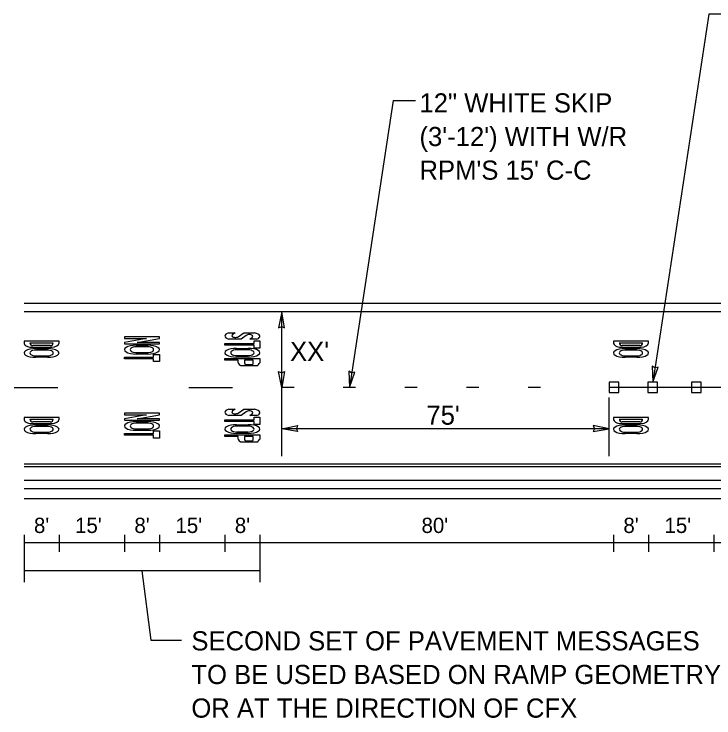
# Model space of a CAD drawing. Extents: x 583689 to 590775, y 1496016 to 1497365.
# Drawn here: x 587322.5 to 587578.1, y 1496182.9 to 1496440 of the extents above; entities that cross this region are included whole.
import ezdxf

# ---------------------------------------------------------------- set-up
doc = ezdxf.new("R2010")
doc.units = 0
for name, color, linetype in [('10', 7, 'Continuous'), ('2', 7, 'Continuous'), ('21', 7, 'Continuous'), ('41', 7, 'Continuous'), ('42', 7, 'Continuous'), ('46', 7, 'Continuous'), ('52', 7, 'Continuous'), ('PavtMessage', 7, 'Continuous'), ('PMStripe6W(10-30)', 7, 'Continuous'), ('TextLabel', 7, 'Continuous')]:
    doc.layers.add(name, color=color, linetype=linetype)

msp = doc.modelspace()

# ---------------------------------------------------------------- linework, layer by layer
at = {"layer": '10'}
for p, q in [((587424.74, 1496303.64), (587420.24, 1496303.64)), ((587447.24, 1496303.64), (587442.74, 1496303.64)), ((587469.74, 1496303.64), (587465.24, 1496303.64)), ((587492.24, 1496303.64), (587487.74, 1496303.64)), ((587514.74, 1496303.64), (587510.24, 1496303.64))]:
    msp.add_line(p, q, dxfattribs=at)
at = {"layer": '2'}
for p, q in [((587663.57, 1496331.25), (587326.15, 1496331.25)), ((587635.53, 1496303.64), (587539.85, 1496303.64)), ((587326.15, 1496274.75), (587663.58, 1496274.75)), ((587387.69, 1496275.75), (587663.57, 1496275.75))]:
    msp.add_line(p, q, dxfattribs=at)
for points in [[(587539.85, 1496301.74), (587543.4, 1496301.74), (587543.4, 1496305.54), (587539.85, 1496305.54)], [(587554.02, 1496301.74), (587557.57, 1496301.74), (587557.57, 1496305.54), (587554.02, 1496305.54)], [(587569.96, 1496301.74), (587573.52, 1496301.74), (587573.52, 1496305.54), (587569.97, 1496305.54)]]:
    msp.add_lwpolyline(points, close=True, dxfattribs=at)
at = {"layer": '21'}
for p, q in [((587576.23, 1496440.04), (587555.8, 1496305.54)), ((587583.82, 1496440.04), (587576.23, 1496440.04)), ((587460.91, 1496408.42), (587444.99, 1496303.64)), ((587460.91, 1496408.42), (587469.14, 1496408.42)), ((587420.24, 1496278.52), (587420.24, 1496331.25)), ((587539.85, 1496278.52), (587539.85, 1496300.03)), ((587539.85, 1496288.57), (587420.24, 1496288.57)), ((587326.15, 1496249.83), (587326.15, 1496232.5)), ((587338.9, 1496249.83), (587338.9, 1496243.54)), ((587362.83, 1496249.83), (587362.83, 1496243.54)), ((587375.58, 1496249.83), (587375.58, 1496243.54)), ((587399.51, 1496249.83), (587399.51, 1496243.54)), ((587412.26, 1496249.83), (587412.26, 1496232.5)), ((587541.44, 1496249.83), (587541.44, 1496243.54)), ((587554.2, 1496249.83), (587554.2, 1496243.54)), ((587578.12, 1496249.83), (587578.12, 1496243.54)), ((587412.26, 1496246.88), (587326.15, 1496246.88)), ((587541.44, 1496246.88), (587412.26, 1496246.88)), ((587635.53, 1496246.88), (587541.44, 1496246.88)), ((587412.26, 1496236.69), (587326.15, 1496236.69)), ((587369.21, 1496236.69), (587372.4, 1496211.31)), ((587372.4, 1496211.31), (587383.61, 1496211.31))]:
    msp.add_line(p, q, dxfattribs=at)
at = {"layer": '41'}
msp.add_line((587326.15, 1496275.75), (587663.57, 1496275.75), dxfattribs=at)
at = {"layer": '42'}
for p, q in [((587663.57, 1496334.25), (587326.15, 1496334.25)), ((587326.15, 1496269.75), (587663.57, 1496269.75)), ((587663.57, 1496263), (587326.15, 1496263))]:
    msp.add_line(p, q, dxfattribs=at)
at = {"layer": '46'}
msp.add_line((587326.15, 1496266.75), (587663.57, 1496266.75), dxfattribs=at)
at = {"layer": '52'}
for p, q in [((587420.24, 1496331.25), (587419.12, 1496325.45)), ((587421.32, 1496325.45), (587420.24, 1496331.25)), ((587419.12, 1496325.45), (587420.24, 1496325.89)), ((587420.24, 1496325.89), (587421.32, 1496325.45)), ((587420.24, 1496303.64), (587419.12, 1496309.44)), ((587419.12, 1496309.44), (587420.24, 1496309)), ((587420.24, 1496309), (587421.32, 1496309.44)), ((587421.32, 1496309.44), (587420.24, 1496303.64)), ((587445.79, 1496308.94), (587444.79, 1496309.53)), ((587444.79, 1496309.53), (587444.99, 1496303.64)), ((587556.6, 1496310.84), (587555.6, 1496311.43)), ((587555.6, 1496311.43), (587555.8, 1496305.54)), ((587555.8, 1496305.54), (587557.77, 1496311.1)), ((587557.77, 1496311.1), (587556.6, 1496310.84)), ((587444.99, 1496303.64), (587446.97, 1496309.2)), ((587446.97, 1496309.2), (587445.79, 1496308.94)), ((587420.24, 1496288.57), (587426.04, 1496289.69)), ((587426.04, 1496289.69), (587425.6, 1496288.57)), ((587539.85, 1496288.57), (587534.05, 1496289.69)), ((587534.05, 1496289.69), (587534.49, 1496288.57)), ((587426.04, 1496287.49), (587420.24, 1496288.57)), ((587425.6, 1496288.57), (587426.04, 1496287.49)), ((587534.49, 1496288.57), (587534.05, 1496287.49)), ((587534.05, 1496287.49), (587539.85, 1496288.57))]:
    msp.add_line(p, q, dxfattribs=at)
at = {"layer": 'PavtMessage'}
for p, q in [((587400.95, 1496323.63), (587403.27, 1496323.63)), ((587403.27, 1496323.63), (587402.26, 1496322.97)), ((587404.4, 1496322.18), (587406.46, 1496323.63)), ((587407.25, 1496322.66), (587405.41, 1496321.24)), ((587406.46, 1496323.63), (587410.36, 1496323.63)), ((587338.91, 1496320.51), (587326.15, 1496320.51)), ((587326.15, 1496320.51), (587326.15, 1496319.97)), ((587328.28, 1496319.97), (587336.79, 1496319.97)), ((587338.91, 1496319.97), (587338.91, 1496320.51)), ((587375.59, 1496322.11), (587362.83, 1496322.11)), ((587362.83, 1496322.11), (587362.83, 1496321.57)), ((587362.83, 1496321.57), (587370.8, 1496321.57)), ((587370.8, 1496321.57), (587362.83, 1496320.11)), ((587362.83, 1496320.11), (587362.83, 1496319.58)), ((587367.45, 1496320.11), (587375.59, 1496321.57)), ((587375.59, 1496320.11), (587367.45, 1496320.11)), ((587375.59, 1496321.57), (587375.59, 1496322.11)), ((587375.59, 1496319.58), (587375.59, 1496320.11)), ((587405.41, 1496321.24), (587400.95, 1496321.24)), ((587408.56, 1496321.24), (587409.48, 1496321.93)), ((587411.18, 1496321.24), (587408.56, 1496321.24)), ((587410.14, 1496320.71), (587412.26, 1496320.71)), ((587410.14, 1496319.64), (587410.14, 1496320.71)), ((587412.26, 1496320.71), (587412.26, 1496318.05)), ((587554.2, 1496320.51), (587541.45, 1496320.51)), ((587541.45, 1496320.51), (587541.45, 1496319.97)), ((587543.57, 1496319.97), (587552.08, 1496319.97)), ((587554.2, 1496319.97), (587554.2, 1496320.51)), ((587328.81, 1496318.38), (587336.25, 1496318.38)), ((587335.72, 1496318.91), (587329.34, 1496318.91)), ((587330.4, 1496317.85), (587334.66, 1496317.85)), ((587334.66, 1496317.32), (587330.4, 1496317.32)), ((587362.83, 1496319.58), (587375.59, 1496319.58)), ((587367.08, 1496319.05), (587371.33, 1496319.05)), ((587371.33, 1496318.52), (587367.08, 1496318.52)), ((587399.51, 1496319.11), (587399.51, 1496319.64)), ((587399.51, 1496319.64), (587410.14, 1496319.64)), ((587410.14, 1496319.11), (587399.51, 1496319.11)), ((587403.76, 1496317.92), (587408.01, 1496317.92)), ((587408.01, 1496317.38), (587403.76, 1496317.38)), ((587410.14, 1496318.05), (587410.14, 1496319.11)), ((587412.26, 1496318.05), (587410.14, 1496318.05)), ((587544.1, 1496318.38), (587551.55, 1496318.38)), ((587551.01, 1496318.91), (587544.64, 1496318.91)), ((587545.7, 1496317.85), (587549.95, 1496317.85)), ((587549.95, 1496317.32), (587545.7, 1496317.32)), ((587330.4, 1496315.19), (587334.66, 1496315.19)), ((587334.66, 1496314.66), (587330.4, 1496314.66)), ((587362.83, 1496314.12), (587362.83, 1496314.65)), ((587362.83, 1496314.65), (587373.46, 1496314.65)), ((587367.08, 1496316.39), (587371.33, 1496316.39)), ((587371.33, 1496315.86), (587367.08, 1496315.86)), ((587373.46, 1496315.72), (587375.59, 1496315.72)), ((587373.46, 1496314.65), (587373.46, 1496315.72)), ((587375.59, 1496315.72), (587375.59, 1496313.06)), ((587403.76, 1496315.26), (587408.01, 1496315.26)), ((587408.01, 1496314.73), (587403.76, 1496314.73)), ((587545.7, 1496315.19), (587549.95, 1496315.19)), ((587549.95, 1496314.66), (587545.7, 1496314.66)), ((587373.46, 1496314.12), (587362.83, 1496314.12)), ((587373.46, 1496313.06), (587373.46, 1496314.12)), ((587375.59, 1496313.06), (587373.46, 1496313.06)), ((587399.51, 1496314.19), (587412.26, 1496314.19)), ((587399.51, 1496313.66), (587399.51, 1496314.19)), ((587404.29, 1496313.66), (587399.51, 1496313.66)), ((587404.29, 1496312.65), (587404.29, 1496313.66)), ((587409.87, 1496313.66), (587406.68, 1496313.66)), ((587406.68, 1496313.66), (587406.68, 1496312.6)), ((587407.09, 1496312.07), (587409.47, 1496312.07)), ((587409.87, 1496312.6), (587409.87, 1496313.66)), ((587412.26, 1496314.19), (587412.26, 1496312.65)), ((587411.2, 1496311.54), (587405.36, 1496311.54)), ((587375.59, 1496294.22), (587362.83, 1496294.22)), ((587362.83, 1496294.22), (587362.83, 1496293.69)), ((587375.59, 1496293.69), (587375.59, 1496294.22)), ((587400.95, 1496295.74), (587403.27, 1496295.74)), ((587403.27, 1496295.74), (587402.26, 1496295.08)), ((587404.4, 1496294.29), (587406.46, 1496295.74)), ((587407.25, 1496294.77), (587405.41, 1496293.35)), ((587406.46, 1496295.74), (587410.36, 1496295.74)), ((587408.56, 1496293.35), (587409.48, 1496294.05)), ((587338.91, 1496292.62), (587326.15, 1496292.62)), ((587326.15, 1496292.62), (587326.15, 1496292.09)), ((587328.28, 1496292.09), (587336.79, 1496292.09)), ((587338.91, 1496292.09), (587338.91, 1496292.62)), ((587362.83, 1496293.69), (587370.8, 1496293.69)), ((587370.8, 1496293.69), (587362.83, 1496292.22)), ((587362.83, 1496292.22), (587362.83, 1496291.69)), ((587362.83, 1496291.69), (587375.59, 1496291.69)), ((587367.45, 1496292.22), (587375.59, 1496293.69)), ((587375.59, 1496292.22), (587367.45, 1496292.22)), ((587375.59, 1496291.69), (587375.59, 1496292.22)), ((587399.51, 1496291.22), (587399.51, 1496291.76)), ((587399.51, 1496291.76), (587410.14, 1496291.76)), ((587405.41, 1496293.35), (587400.95, 1496293.35)), ((587411.18, 1496293.35), (587408.56, 1496293.35)), ((587410.14, 1496292.82), (587412.26, 1496292.82)), ((587410.14, 1496291.76), (587410.14, 1496292.82)), ((587412.26, 1496292.82), (587412.26, 1496290.16)), ((587554.2, 1496292.62), (587541.45, 1496292.62)), ((587541.45, 1496292.62), (587541.45, 1496292.09)), ((587543.57, 1496292.09), (587552.08, 1496292.09)), ((587554.2, 1496292.09), (587554.2, 1496292.62)), ((587328.81, 1496290.49), (587336.25, 1496290.49)), ((587335.72, 1496291.02), (587329.34, 1496291.02)), ((587330.4, 1496289.96), (587334.66, 1496289.96)), ((587334.66, 1496289.43), (587330.4, 1496289.43)), ((587367.08, 1496291.16), (587371.33, 1496291.16)), ((587371.33, 1496290.63), (587367.08, 1496290.63)), ((587410.14, 1496291.22), (587399.51, 1496291.22)), ((587403.76, 1496290.03), (587408.01, 1496290.03)), ((587408.01, 1496289.5), (587403.76, 1496289.5)), ((587410.14, 1496290.16), (587410.14, 1496291.22)), ((587412.26, 1496290.16), (587410.14, 1496290.16)), ((587544.1, 1496290.49), (587551.55, 1496290.49)), ((587551.01, 1496291.02), (587544.64, 1496291.02)), ((587545.7, 1496289.96), (587549.95, 1496289.96)), ((587549.95, 1496289.43), (587545.7, 1496289.43)), ((587330.4, 1496287.3), (587334.66, 1496287.3)), ((587334.66, 1496286.77), (587330.4, 1496286.77)), ((587362.83, 1496286.24), (587362.83, 1496286.77)), ((587362.83, 1496286.77), (587373.46, 1496286.77)), ((587367.08, 1496288.5), (587371.33, 1496288.5)), ((587371.33, 1496287.97), (587367.08, 1496287.97)), ((587373.46, 1496287.83), (587375.59, 1496287.83)), ((587373.46, 1496286.77), (587373.46, 1496287.83)), ((587375.59, 1496287.83), (587375.59, 1496285.17)), ((587399.51, 1496286.31), (587412.26, 1496286.31)), ((587399.51, 1496285.77), (587399.51, 1496286.31)), ((587403.76, 1496287.37), (587408.01, 1496287.37)), ((587408.01, 1496286.84), (587403.76, 1496286.84)), ((587412.26, 1496286.31), (587412.26, 1496284.76)), ((587545.7, 1496287.3), (587549.95, 1496287.3)), ((587549.95, 1496286.77), (587545.7, 1496286.77)), ((587373.46, 1496286.24), (587362.83, 1496286.24)), ((587373.46, 1496285.17), (587373.46, 1496286.24)), ((587375.59, 1496285.17), (587373.46, 1496285.17)), ((587404.29, 1496285.77), (587399.51, 1496285.77)), ((587404.29, 1496284.76), (587404.29, 1496285.77)), ((587409.87, 1496285.77), (587406.68, 1496285.77)), ((587406.68, 1496285.77), (587406.68, 1496284.71)), ((587407.09, 1496284.18), (587409.47, 1496284.18)), ((587409.87, 1496284.71), (587409.87, 1496285.77)), ((587411.2, 1496283.65), (587405.36, 1496283.65))]:
    msp.add_line(p, q, dxfattribs=at)
for centre, start, end in [((587329.34, 1496319.97), 180, 270), ((587335.72, 1496319.97), 270, 0), ((587544.64, 1496319.97), 180, 270), ((587551.02, 1496319.97), 270, 0), ((587329.34, 1496292.09), 180, 270), ((587335.72, 1496292.09), 270, 0), ((587544.64, 1496292.09), 180, 270), ((587551.02, 1496292.09), 270, 0)]:
    msp.add_arc(centre, 1.06, start, end, dxfattribs=at)
for centre, major_axis, ratio, start_param, end_param in [((587403.76, 1496322.43), (-4.25, 0), 0.375, 5.435123, 7.131247), ((587403.32, 1496322.57), (1.33, 0), 0.5, 2.490106, 5.666015), ((587408.37, 1496322.3), (1.33, 0), 0.5, 5.699287, 8.851109), ((587408.01, 1496322.3), (4.25, 0), 0.375, 5.553458, 7.268296), ((587328.81, 1496319.97), (2.66, 0), 0.6, 3.141593, 4.71335), ((587336.25, 1496319.97), (2.66, 0), 0.6, 4.71335, 6.283185), ((587544.1, 1496319.97), (2.66, 0), 0.6, 3.141593, 4.71335), ((587551.55, 1496319.97), (2.66, 0), 0.6, 4.71335, 6.283185), ((587330.4, 1496316.25), (4.25, 0), 0.375, 1.570796, 4.712389), ((587330.4, 1496316.25), (2.13, 0), 0.5, 1.570796, 4.712389), ((587334.66, 1496316.25), (4.25, 0), 0.375, 4.712389, 7.853982), ((587334.66, 1496316.25), (2.13, 0), 0.5, 4.712389, 7.853982), ((587367.08, 1496317.45), (4.25, 0), 0.375, 1.570796, 4.712389), ((587367.08, 1496317.45), (2.13, 0), 0.5, 1.570796, 4.712389), ((587371.33, 1496317.45), (4.25, 0), 0.375, 4.712389, 7.853982), ((587371.33, 1496317.45), (2.13, 0), 0.5, 4.712389, 7.853982), ((587403.76, 1496316.32), (4.25, 0), 0.375, 1.570796, 4.712389), ((587403.76, 1496316.32), (2.13, 0), 0.5, 1.570796, 4.712389), ((587408.01, 1496316.32), (4.25, 0), 0.375, 4.712389, 7.853982), ((587408.01, 1496316.32), (2.13, 0), 0.5, 4.712389, 7.853982), ((587545.7, 1496316.25), (4.25, 0), 0.375, 1.570796, 4.712389), ((587545.7, 1496316.25), (2.13, 0), 0.5, 1.570796, 4.712389), ((587549.95, 1496316.25), (4.25, 0), 0.375, 4.712389, 7.853982), ((587549.95, 1496316.25), (2.13, 0), 0.5, 4.712389, 7.853982), ((587408.28, 1496313.66), (4.25, 0), 0.6875, 3.497014, 3.955933), ((587408.28, 1496312.6), (1.59, 0), 0.5, 3.141593, 3.87132), ((587408.28, 1496312.6), (1.59, 0), 0.5, 5.553458, 6.283185), ((587408.28, 1496313.66), (4.25, 0), 0.6875, 5.468845, 5.927764), ((587403.76, 1496294.55), (-4.25, 0), 0.375, 5.435123, 7.131247), ((587403.32, 1496294.68), (1.33, 0), 0.5, 2.490106, 5.666015), ((587408.37, 1496294.41), (1.33, 0), 0.5, 5.699287, 8.851109), ((587408.01, 1496294.41), (4.25, 0), 0.375, 5.553458, 7.268296), ((587328.81, 1496292.09), (2.66, 0), 0.6, 3.141593, 4.71335), ((587336.25, 1496292.09), (2.66, 0), 0.6, 4.71335, 6.283185), ((587544.1, 1496292.09), (2.66, 0), 0.6, 3.141593, 4.71335), ((587551.55, 1496292.09), (2.66, 0), 0.6, 4.71335, 6.283185), ((587330.4, 1496288.37), (4.25, 0), 0.375, 1.570796, 4.712389), ((587330.4, 1496288.37), (2.13, 0), 0.5, 1.570796, 4.712389), ((587334.66, 1496288.37), (4.25, 0), 0.375, 4.712389, 7.853982), ((587334.66, 1496288.37), (2.13, 0), 0.5, 4.712389, 7.853982), ((587367.08, 1496289.57), (4.25, 0), 0.375, 1.570796, 4.712389), ((587367.08, 1496289.57), (2.13, 0), 0.5, 1.570796, 4.712389), ((587371.33, 1496289.57), (4.25, 0), 0.375, 4.712389, 7.853982), ((587371.33, 1496289.57), (2.13, 0), 0.5, 4.712389, 7.853982), ((587403.76, 1496288.43), (4.25, 0), 0.375, 1.570796, 4.712389), ((587403.76, 1496288.43), (2.13, 0), 0.5, 1.570796, 4.712389), ((587408.01, 1496288.43), (4.25, 0), 0.375, 4.712389, 7.853982), ((587408.01, 1496288.43), (2.13, 0), 0.5, 4.712389, 7.853982), ((587545.7, 1496288.37), (4.25, 0), 0.375, 1.570796, 4.712389), ((587545.7, 1496288.37), (2.13, 0), 0.5, 1.570796, 4.712389), ((587549.95, 1496288.37), (4.25, 0), 0.375, 4.712389, 7.853982), ((587549.95, 1496288.37), (2.13, 0), 0.5, 4.712389, 7.853982), ((587408.28, 1496285.77), (4.25, 0), 0.6875, 3.497014, 3.955933), ((587408.28, 1496284.71), (1.59, 0), 0.5, 3.141593, 3.87132), ((587408.28, 1496284.71), (1.59, 0), 0.5, 5.553458, 6.283185), ((587408.28, 1496285.77), (4.25, 0), 0.6875, 5.468845, 5.927764)]:
    msp.add_ellipse(centre, major_axis=major_axis, ratio=ratio, start_param=start_param, end_param=end_param, dxfattribs=at)
at = {"layer": 'PMStripe6W(10-30)'}
for p, q in [((587322.49, 1496303.64), (587338.44, 1496303.64)), ((587386.28, 1496303.64), (587402.23, 1496303.64))]:
    msp.add_line(p, q, dxfattribs=at)

# ---------------------------------------------------------------- texts
at = {"layer": '21'}
for s, p in [('12" WHITE SKIP', (587470.57, 1496404.09)), ("(3'-12') WITH W/R", (587470.57, 1496391.81)), ("RPM'S 15' C-C", (587470.57, 1496379.53)), ('SECOND SET OF PAVEMENT MESSAGES', (587387.25, 1496207.57)), ('TO BE USED BASED ON RAMP GEOMETRY', (587387.25, 1496195.29)), ('OR AT THE DIRECTION OF CFX', (587387.25, 1496183.01))]:
    msp.add_text(s, height=7, dxfattribs=at).set_placement(p)
for s, p in [("XX'", (587423.3, 1496313.3)), ("75'", (587473.12, 1496290))]:
    msp.add_text(s, height=7, rotation=0.2102, dxfattribs=at).set_placement(p)
at = {"layer": 'TextLabel'}
for s, p in [("8'", (587329.76, 1496250.47)), ("15'", (587344.77, 1496250.47)), ("8'", (587366.44, 1496250.47)), ("15'", (587381.45, 1496250.47)), ("8'", (587403.12, 1496250.47)), ("80'", (587471.32, 1496250.47)), ("8'", (587545.06, 1496250.47)), ("15'", (587560.07, 1496250.47))]:
    msp.add_text(s, height=5.582, dxfattribs=at).set_placement(p)

doc.saveas('drawing.dxf')
